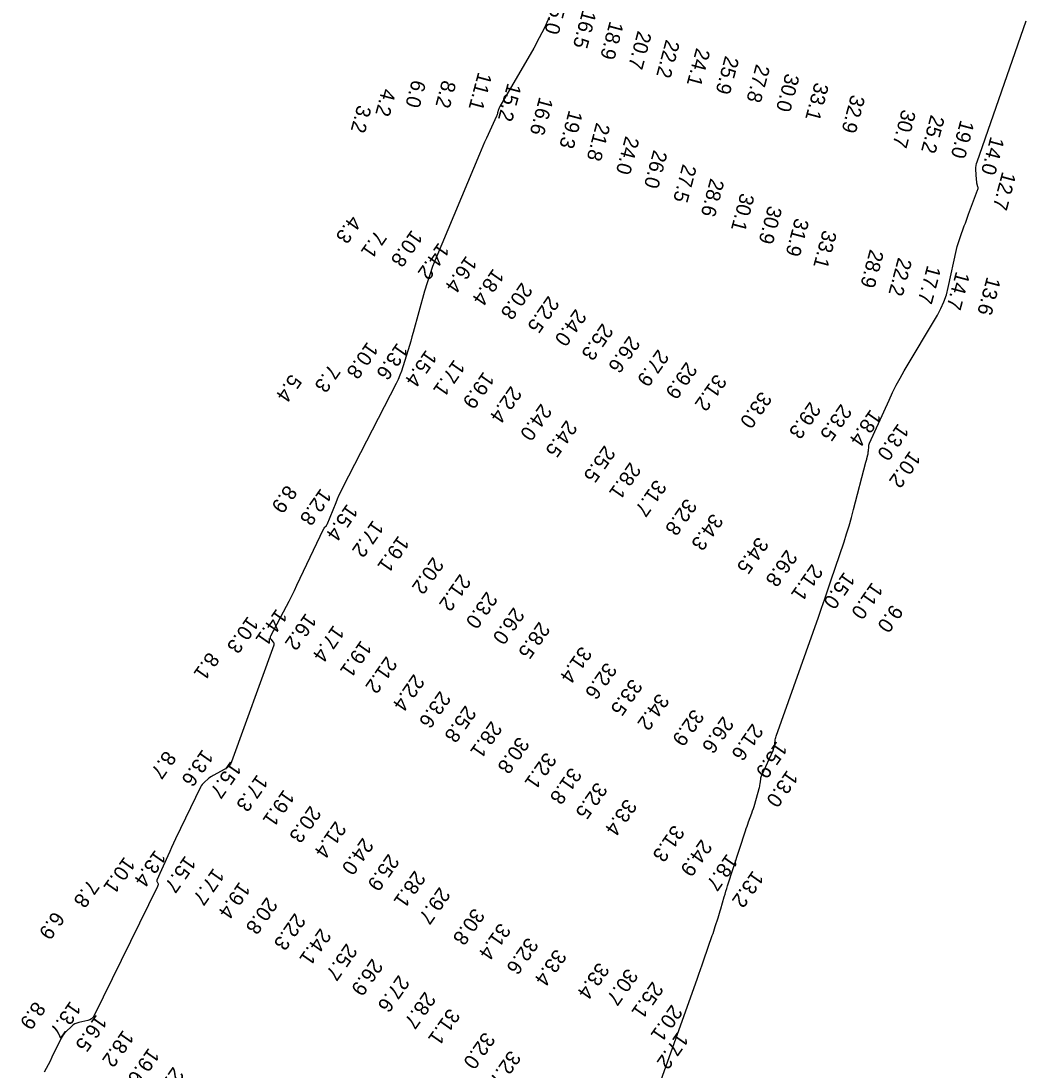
# Model space of a CAD drawing. Extents: x 988130 to 1132882, y 654656 to 841453.
# Drawn here: x 1037585.8 to 1037929.4, y 781612.8 to 781971.3 of the extents above; entities that cross this region are included whole.
import ezdxf

# ---------------------------------------------------------------- set-up
doc = ezdxf.new("R2010")
doc.units = 0
doc.layers.add('V-TOPO-MAJR', color=7, linetype='Continuous')
doc.layers.add('V-TOPO-SOUN', color=7, linetype='Continuous')

msp = doc.modelspace()

# ---------------------------------------------------------------- linework, layer by layer
at = {"layer": 'V-TOPO-MAJR'}
for points in [[(1037766.38, 781972.58), (1037764.76, 781969), (1037762.99, 781965.5), (1037761.09, 781962.06), (1037749.53, 781942.14), (1037749.39, 781941.87), (1037749.26, 781941.6), (1037749.16, 781941.32), (1037749.07, 781941.04), (1037748.76, 781939.88), (1037748.68, 781939.59), (1037748.59, 781939.31), (1037748.48, 781939.03), (1037748.36, 781938.75), (1037744.91, 781931.24), (1037744.3, 781929.89), (1037743.7, 781928.54), (1037743.12, 781927.18), (1037742.54, 781925.82), (1037727.66, 781890.13), (1037726.56, 781887.39), (1037725.56, 781884.61), (1037724.64, 781881.81), (1037723.81, 781878.97), (1037719.9, 781864.82), (1037719.49, 781863.35), (1037719.07, 781861.88), (1037718.63, 781860.41), (1037718.19, 781858.95), (1037716.38, 781853.11), (1037715.89, 781851.66), (1037715.35, 781850.24), (1037714.74, 781848.84), (1037714.08, 781847.47), (1037695.76, 781811.75), (1037695.14, 781810.49), (1037694.53, 781809.22), (1037693.96, 781807.93), (1037693.42, 781806.64), (1037690.36, 781799.12), (1037690.29, 781798.97), (1037690.2, 781798.82), (1037690.1, 781798.69), (1037689.99, 781798.56), (1037689.52, 781798.07), (1037689.41, 781797.95), (1037689.31, 781797.81), (1037689.22, 781797.67), (1037689.14, 781797.52), (1037680.06, 781778.37), (1037679.19, 781776.56), (1037678.3, 781774.76), (1037677.39, 781772.97), (1037676.46, 781771.19), (1037671.11, 781761.11), (1037671.01, 781760.83), (1037670.99, 781760.56), (1037671.06, 781760.3), (1037671.22, 781760.05), (1037672.04, 781759.07), (1037672.21, 781758.81), (1037672.29, 781758.55), (1037672.3, 781758.27), (1037672.23, 781757.97), (1037657.81, 781718.17), (1037657.43, 781717.36), (1037656.93, 781716.66), (1037656.31, 781716.07), (1037655.56, 781715.59), (1037651.57, 781713.5), (1037651.13, 781713.25), (1037650.72, 781712.98), (1037650.31, 781712.69), (1037649.92, 781712.38), (1037648.41, 781711.07), (1037648.05, 781710.73), (1037647.73, 781710.36), (1037647.45, 781709.95), (1037647.22, 781709.52), (1037638.66, 781691.76), (1037637.98, 781690.34), (1037637.31, 781688.91), (1037636.66, 781687.48), (1037636.02, 781686.04), (1037632.32, 781677.7), (1037632.27, 781677.56), (1037632.26, 781677.41), (1037632.28, 781677.27), (1037632.33, 781677.12), (1037632.68, 781676.4), (1037632.71, 781676.33), (1037632.72, 781676.26), (1037632.72, 781676.19), (1037632.7, 781676.12), (1037632.59, 781675.83), (1037632.56, 781675.75), (1037632.53, 781675.68), (1037632.5, 781675.61), (1037632.47, 781675.54), (1037610.86, 781631.45), (1037610.47, 781630.83), (1037609.98, 781630.34), (1037609.38, 781629.98), (1037608.69, 781629.75), (1037605.55, 781629.05), (1037604.9, 781628.86), (1037604.29, 781628.59), (1037603.72, 781628.24), (1037603.19, 781627.81), (1037601.17, 781625.91), (1037600.69, 781625.42), (1037600.26, 781624.89), (1037599.88, 781624.32), (1037599.56, 781623.72), (1037596.42, 781617.18), (1037595.79, 781615.89), (1037595.13, 781614.61), (1037594.44, 781613.35), (1037593.72, 781612.1)], [(1037797.38, 781589.03), (1037816.96, 781643.91), (1037817.54, 781645.54), (1037818.11, 781647.18), (1037818.69, 781648.81), (1037819.26, 781650.45), (1037822.15, 781658.75), (1037822.41, 781659.51), (1037822.67, 781660.27), (1037822.92, 781661.04), (1037823.16, 781661.8), (1037824.14, 781664.86), (1037824.39, 781665.63), (1037824.62, 781666.4), (1037824.85, 781667.17), (1037825.08, 781667.94), (1037826.25, 781672.02), (1037826.53, 781672.95), (1037826.81, 781673.89), (1037827.1, 781674.82), (1037827.4, 781675.75), (1037833.52, 781694.6), (1037833.77, 781695.36), (1037834.03, 781696.12), (1037834.29, 781696.87), (1037834.57, 781697.62), (1037835.68, 781700.62), (1037835.95, 781701.37), (1037836.21, 781702.13), (1037836.45, 781702.89), (1037836.67, 781703.66), (1037838.17, 781708.99), (1037838.27, 781709.39), (1037838.36, 781709.79), (1037838.44, 781710.19), (1037838.5, 781710.59), (1037838.71, 781712.22), (1037838.78, 781712.62), (1037838.88, 781713.01), (1037839, 781713.4), (1037839.16, 781713.77), (1037842.92, 781722.01), (1037843.08, 781722.39), (1037843.21, 781722.79), (1037843.31, 781723.19), (1037843.38, 781723.61), (1037843.61, 781725.27), (1037843.68, 781725.69), (1037843.77, 781726.1), (1037843.88, 781726.5), (1037844.01, 781726.9), (1037858.41, 781767.58), (1037859.5, 781770.69), (1037860.59, 781773.8), (1037861.66, 781776.91), (1037862.71, 781780.03), (1037867.18, 781793.27), (1037868.08, 781796.03), (1037868.93, 781798.8), (1037869.73, 781801.58), (1037870.48, 781804.38), (1037874.69, 781820.58), (1037874.77, 781820.9), (1037874.85, 781821.21), (1037874.93, 781821.53), (1037875.01, 781821.84), (1037875.32, 781823.1), (1037875.39, 781823.42), (1037875.45, 781823.73), (1037875.49, 781824.05), (1037875.52, 781824.38), (1037875.61, 781825.73), (1037875.64, 781826.06), (1037875.71, 781826.38), (1037875.8, 781826.7), (1037875.93, 781827), (1037882.61, 781841.76), (1037883.8, 781844.3), (1037885.06, 781846.81), (1037886.39, 781849.28), (1037887.79, 781851.72), (1037899.11, 781870.8), (1037900.32, 781873.05), (1037901.35, 781875.37), (1037902.18, 781877.76), (1037902.82, 781880.23), (1037905.65, 781893.2), (1037905.9, 781894.24), (1037906.18, 781895.26), (1037906.49, 781896.28), (1037906.84, 781897.28), (1037908.3, 781901.28), (1037908.67, 781902.27), (1037909.04, 781903.27), (1037909.41, 781904.27), (1037909.78, 781905.26), (1037912.87, 781913.45), (1037912.96, 781913.75), (1037913, 781914.05), (1037912.99, 781914.36), (1037912.94, 781914.66), (1037912.64, 781915.89), (1037912.58, 781916.2), (1037912.53, 781916.51), (1037912.49, 781916.82), (1037912.47, 781917.14), (1037912.3, 781920.58), (1037912.3, 781921.25), (1037912.37, 781921.92), (1037912.49, 781922.58), (1037912.69, 781923.22), (1037929.4, 781971.35)]]:
    msp.add_lwpolyline(points, dxfattribs=at)

# ---------------------------------------------------------------- texts
at = {"layer": 'V-TOPO-SOUN'}
for s, rotation, p in [('15.0 ', 255, (1037768.06, 781980.14)), ('16.5 ', 255, (1037777.82, 781975.29)), ('18.9 ', 255, (1037787.13, 781971.49)), ('20.7 ', 255, (1037796.69, 781968.18)), ('22.2 ', 255, (1037806.32, 781965.19)), ('24.1 ', 255, (1037816.72, 781962.32)), ('25.9 ', 255, (1037826.58, 781959.63)), ('27.8 ', 255, (1037837.15, 781956.78)), ('11.1 ', 255, (1037742.15, 781954.1)), ('30.0 ', 255, (1037847.24, 781953.65)), ('6.0', 255, (1037719.56, 781951.47)), ('8.2', 255, (1037729.86, 781951.34)), ('15.2 ', 255, (1037752.2, 781950.35)), ('33.1 ', 255, (1037857.25, 781950.57)), ('4.2', 255, (1037709.31, 781948.48)), ('32.9 ', 255, (1037869.64, 781946.38)), ('3.2', 255, (1037700.9, 781942.85)), ('16.6 ', 255, (1037763.06, 781945.6)), ('19.3 ', 255, (1037773.17, 781941.06)), ('30.7 ', 255, (1037887.02, 781941.33)), ('25.2 ', 255, (1037896.86, 781939.45)), ('21.8 ', 255, (1037782.53, 781936.8)), ('19.0 ', 255, (1037907.01, 781937.71)), ('24.0 ', 255, (1037792.5, 781932.21)), ('14.0 ', 255, (1037917.31, 781932.07)), ('26.0 ', 255, (1037802.1, 781927.47)), ('27.5 ', 255, (1037812.08, 781922.63)), ('28.6 ', 255, (1037821.53, 781917.77)), ('12.7 ', 255, (1037921.3, 781920.05)), ('30.1 ', 255, (1037831.86, 781912.77)), ('30.9 ', 255, (1037841.29, 781908.45)), ('4.3', 235, (1037698.5, 781905.19)), ('31.9 ', 255, (1037850.51, 781904.23)), ('7.1', 235, (1037707.09, 781900.08)), ('10.8 ', 235, (1037719.46, 781900.21)), ('33.1 ', 255, (1037860, 781900.11)), ('14.2 ', 235, (1037728.64, 781895.87)), ('28.9 ', 255, (1037876.07, 781893.5)), ('16.4 ', 235, (1037738.08, 781891.37)), ('22.2 ', 255, (1037885.7, 781890.7)), ('18.4 ', 235, (1037747.31, 781886.99)), ('17.7 ', 255, (1037895.66, 781888.04)), ('14.7 ', 255, (1037905.5, 781885.97)), ('20.8 ', 235, (1037757.01, 781882.23)), ('13.6 ', 255, (1037916.05, 781884.11)), ('22.5 ', 235, (1037766.15, 781877.67)), ('24.0 ', 235, (1037775.46, 781873.16)), ('25.3 ', 235, (1037784.63, 781868.29)), ('26.6 ', 235, (1037793.78, 781864.01)), ('10.8 ', 235, (1037704.29, 781861.96)), ('13.6 ', 235, (1037714.5, 781861.63)), ('15.4 ', 235, (1037724.35, 781859.21)), ('27.9 ', 235, (1037803.63, 781859.37)), ('7.3', 235, (1037691.26, 781854.27)), ('17.1 ', 235, (1037733.95, 781855.91)), ('29.9 ', 235, (1037813.32, 781855.09)), ('5.4', 235, (1037678.1, 781850.95)), ('19.9 ', 235, (1037744, 781851.76)), ('31.2 ', 235, (1037823.37, 781850.99)), ('22.4 ', 235, (1037753.33, 781846.85)), ('33.0 ', 235, (1037838.8, 781845.06)), ('24.0 ', 235, (1037763.63, 781840.84)), ('29.3 ', 235, (1037855.57, 781841.47)), ('23.5 ', 235, (1037866.17, 781840.72)), ('18.4 ', 235, (1037876.28, 781838.88)), ('24.5 ', 235, (1037772.32, 781835.17)), ('13.0 ', 235, (1037885.72, 781834.05)), ('25.5 ', 235, (1037785.34, 781826.55)), ('10.2 ', 235, (1037889.76, 781824.72)), ('28.1 ', 235, (1037794.08, 781820.81)), ('31.7 ', 235, (1037802.8, 781814.92)), ('8.9', 235, (1037676.53, 781813.05)), ('12.8 ', 235, (1037688.34, 781811.89)), ('15.4 ', 235, (1037697.36, 781806.57)), ('32.8 ', 235, (1037813.22, 781808.46)), ('34.3 ', 235, (1037822.18, 781803.33)), ('17.2 ', 235, (1037706.19, 781801)), ('19.1 ', 235, (1037714.9, 781795.74)), ('34.5 ', 235, (1037837.72, 781795.32)), ('20.2 ', 235, (1037726.67, 781788.41)), ('26.8 ', 235, (1037847.56, 781790.93)), ('21.1 ', 235, (1037856.29, 781786.04)), ('21.2 ', 235, (1037735.95, 781782.61)), ('15.0 ', 235, (1037867.29, 781783.33)), ('11.0 ', 235, (1037876.83, 781779.82)), ('23.0 ', 235, (1037745.05, 781776.62)), ('14.1 ', 235, (1037673.21, 781770.74)), ('26.0 ', 235, (1037754.26, 781771.22)), ('9.0', 235, (1037883.65, 781772.24)), ('10.3 ', 235, (1037663.41, 781768.17)), ('16.2 ', 235, (1037683.23, 781769.25)), ('17.4 ', 235, (1037692.74, 781765.17)), ('28.5 ', 235, (1037763, 781766.29)), ('19.1 ', 235, (1037702.1, 781759.95)), ('31.4 ', 235, (1037777.32, 781757.95)), ('8.1', 235, (1037649.94, 781755.94)), ('21.2 ', 235, (1037710.76, 781754.49)), ('32.6 ', 235, (1037785.85, 781752.46)), ('22.4 ', 235, (1037720.12, 781748.39)), ('33.5 ', 235, (1037794.57, 781746.85)), ('23.6 ', 235, (1037729.08, 781742.63)), ('34.2 ', 235, (1037803.73, 781741.87)), ('25.8 ', 235, (1037737.78, 781737.69)), ('32.9 ', 235, (1037815.65, 781736.5)), ('28.1 ', 235, (1037746.62, 781732.37)), ('26.6 ', 235, (1037825.82, 781734.01)), ('21.6 ', 235, (1037835.91, 781731.53)), ('30.8 ', 235, (1037755.91, 781727.05)), ('15.9 ', 235, (1037844.17, 781725.45)), ('8.7', 235, (1037635.18, 781722.26)), ('13.6 ', 235, (1037647.92, 781722.7)), ('32.1 ', 235, (1037765.2, 781721.73)), ('15.7 ', 235, (1037657.55, 781718.62)), ('17.3 ', 235, (1037666.62, 781714.09)), ('31.8 ', 235, (1037773.82, 781716.57)), ('13.0 ', 235, (1037847.81, 781715.59)), ('32.5 ', 235, (1037782.58, 781711.51)), ('19.1 ', 235, (1037675.68, 781708.96)), ('20.3 ', 235, (1037684.74, 781703.42)), ('33.4 ', 235, (1037792.68, 781705.82)), ('21.4 ', 235, (1037693.36, 781698.14)), ('31.3 ', 235, (1037808.95, 781696.9)), ('24.0 ', 235, (1037702.67, 781692.47)), ('24.9 ', 235, (1037818.43, 781691.95)), ('13.4 ', 235, (1037631.73, 781688.34)), ('10.1 ', 235, (1037621.21, 781686.01)), ('15.7 ', 235, (1037642.01, 781686.37)), ('25.9 ', 235, (1037711.47, 781686.98)), ('18.7 ', 235, (1037827.23, 781687.04)), ('17.7 ', 235, (1037651.67, 781682.12)), ('28.1 ', 235, (1037720.44, 781681.24)), ('13.2 ', 235, (1037836.08, 781681.29)), ('7.8', 235, (1037608.87, 781678.2)), ('19.4 ', 235, (1037660.55, 781677.42)), ('29.7 ', 235, (1037728.91, 781675.62)), ('20.8 ', 235, (1037669.86, 781672.16)), ('6.9', 235, (1037597.04, 781667.34)), ('22.3 ', 235, (1037679.46, 781666.71)), ('30.8 ', 235, (1037740.65, 781668.47)), ('31.4 ', 235, (1037749.54, 781663.39)), ('24.1 ', 235, (1037688.2, 781661.55)), ('25.7 ', 235, (1037697.13, 781656.37)), ('32.6 ', 235, (1037758.99, 781658.45)), ('33.4 ', 235, (1037768.62, 781654.47)), ('26.9 ', 235, (1037705.9, 781651.17)), ('33.4 ', 235, (1037783.25, 781649.94)), ('27.6 ', 235, (1037714.95, 781645.54)), ('30.7 ', 235, (1037793.08, 781647.88)), ('25.1 ', 235, (1037801.75, 781643.35)), ('28.7 ', 235, (1037723.93, 781639.87)), ('8.9', 235, (1037590.53, 781636.57)), ('13.7 ', 235, (1037602.72, 781636.68)), ('31.1 ', 235, (1037732.22, 781634.22)), ('20.1 ', 235, (1037808.29, 781635.47)), ('16.5 ', 235, (1037611.61, 781632.04)), ('18.2 ', 235, (1037620.77, 781626.78)), ('32.0 ', 235, (1037744.23, 781626.11)), ('17.2 ', 235, (1037810.37, 781626.1)), ('19.6 ', 235, (1037629.52, 781620.66)), ('32.7 ', 235, (1037753.01, 781619.84)), ('21.5 ', 235, (1037637.86, 781614.18))]:
    msp.add_text(s, height=5, rotation=rotation, dxfattribs=at).set_placement(p)

doc.saveas('drawing.dxf')
